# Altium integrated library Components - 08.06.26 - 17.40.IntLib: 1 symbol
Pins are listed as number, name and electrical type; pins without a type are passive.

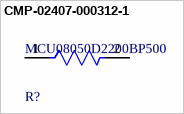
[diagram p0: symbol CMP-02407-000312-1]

## CMP-02407-000312-1
designator R?, comment MCU08050D2200BP500
RES 1.05K OHM 0.5% 1/5W 0805; Resistance: 220R; Tolerance: 0.1%; Temperature Coefficient: 25ppm/°C; Max Power Dissipation: 125mW
footprint FP-MCU0805-IPC_C
footprint FP-MCU0805-IPC_A
footprint FP-MCU0805-IPC_B
footprint FP-MCU0805-MFG
pins: 1, 2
